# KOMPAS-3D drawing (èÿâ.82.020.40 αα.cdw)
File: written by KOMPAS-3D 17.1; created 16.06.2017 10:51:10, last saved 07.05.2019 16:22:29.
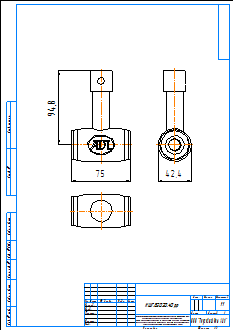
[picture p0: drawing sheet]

Sheet 1: A3, portrait

Title block, sheet 1: name: КШГ.82.020.40 рр; material: Внимание! Данный продукт является объектом авторского права ООО «Торговый Дом АДЛ». / Запрещается изменение, копирование, распространение / (в том числе путем копирования на другие сайты и ресурсы в Интернете) / или любое иное использование информации и объектов без предварительного / согласия правообладателя (ООО «Торговый Дом АДЛ»).; scale: 1:1; sheets: 1; organisation: ООО "Торговый дом АДЛ"; sheet format: A3; stored path: C:\Users\tra\Desktop\2д чертежи\Шаровые краны БИВАЛ\КШ_Бивал_серия_82_85\KOMPAS 2D\КШГ.82.020.40 рр.cdw

Views: Спереди 1, Проекционный вид 2, Проекционный вид 3
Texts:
  Klimkovich
  ADL
Dimensions and other numbers on the sheet: 75; 94,8; 42,4; 1:1; 1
